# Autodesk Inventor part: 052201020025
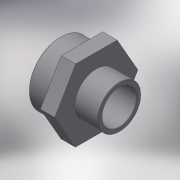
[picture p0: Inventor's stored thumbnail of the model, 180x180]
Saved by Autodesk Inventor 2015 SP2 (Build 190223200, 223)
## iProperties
Created: 2017-10
Part Number: 052201020025
Material: Generic
Description: PLASSON SOCKET NIPPLE THR. P 2"-2.1/2"
Document SubType Name: Modeling
Designer: KIM
Density: 1 g/cm^3
Appearance: Default
Author: KIM
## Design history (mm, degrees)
derived "052201.ipt"
feature "Solid1::052201.ipt"
tag "TaggingFeature1"
body "Solid1"
other parameters: "d0" = 69, "d2" = 95, "d13" = 0, "d14" = 0.72226, "d17" = 26, "d18" = 34.8, "d19" = 89.19911, "d20" = 72.226, "d21" = 59.614, "d22" = 20.8, "d23" = 68.6147, "d24" = 47.6912, "d25" = 29, "d26" = -26, "G_" = 72.226, "R_" = 59.614, "C_" = 95, "lt_1" = 26, "lt_" = 29, "H_" = 69
